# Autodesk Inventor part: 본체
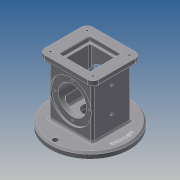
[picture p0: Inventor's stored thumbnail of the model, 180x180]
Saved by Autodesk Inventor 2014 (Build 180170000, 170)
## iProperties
Created: 2019-08
Part Number: 본체
Material: Generic
Document SubType Name: Modeling
Designer: kb542-17
Density: 1 g/cm^3
Appearance: Default
Mass: 384.755 g
Surface Area: 783.577 cm^2
Volume: 384.755 cm^3
Author: kb542-17
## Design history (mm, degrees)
sketch "스케치1"
  geometry: L1 (-37, 33)-(37, 33); L2 (37, 33)-(37, -33); L3 (37, -33)-(-37, -33); L4 (-37, -33)-(-37, 33); L5 (-37, 33)-(37, -33); L6 (37, 33)-(-37, -33); 1 further point
  constraints: 12 end point, 2 midpoint, 2 parallel, 1 horizontal, 1 perpendicular
  dimensions: "d0" = 66 distance of L1.end L2.end; "d1" = 74 distance of L1.start L1.end
extrude "돌출1" new body sketch "스케치1" stored distance "d2" = 88; taper "d3" = 0 deg
sketch "스케치2"
  geometry: L1 (-46, 41)-(46, 41); L2 (46, 41)-(46, -41); L3 (46, -41)-(-46, -41); L4 (-46, -41)-(-46, 41); L5 (-46, 41)-(46, -41); L6 (46, 41)-(-46, -41); 1 further point
  constraints: 12 end point, 2 midpoint, 2 parallel, 1 horizontal, 1 perpendicular
  dimensions: "d4" = 82 distance of L1.end L2.end; "d5" = 92 distance of L1.start L1.end
extrude "돌출2" join sketch "스케치2" distance "d6" = 10; taper "d7" = 0 deg
sketch "스케치3"
  geometry: C1 r 67.5 at (0, 0); 1 further point
  constraints: 1 centre point, 1 coincident
  dimensions: "d8" = 135 diameter of C1
extrude "돌출3" join sketch "스케치3" distance "d9" = 10; taper "d10" = 0 deg
sketch "스케치4"
  geometry: L1 (-33, 44)-(-33, -44) reference; L2 (33, -44)-(33, 44) reference; L3 (-33, 0)-(33, 0); L4 (-33, 35)-(-30, 35); L5 (-30, 35)-(-30, 24); L6 (-30, 24)-(30, 24); L7 (30, 24)-(30, 35); L8 (30, 35)-(33, 35); 2 further points
  constraints: 12 end point, 3 midpoint, 3 parallel, 2 point on line, 1 coincident, 1 collinear, 1 perpendicular
  dimensions: "d11" = 3 distance between parallel lines of L1 L5; "d12" = 3 distance between parallel lines of L2 L7; "d13" = 70 diameter of L4 L3; "d14" = 48 diameter of L6 L3; "d15" = 70 diameter of L8 L3
revolve "회전1" sketch "스케치4" stored, may be unused: angle "d16" = 90 deg
sketch "스케치5"
  geometry: C1 r 67.5 at (0, 0) reference; C2 r 25 at (0, 0)
  constraints: 1 centre point, 1 coincident
  dimensions: "d17" = 50 diameter of C2
extrude "돌출4" cut sketch "스케치5" distance "d18" = 18; taper "d19" = 0 deg
sketch "스케치6"
  geometry: L1 (-26, 26)-(26, 26); L2 (26, 26)-(26, -26); L3 (26, -26)-(-26, -26); L4 (-26, -26)-(-26, 26); L5 (-26, 26)-(26, -26); L6 (26, 26)-(-26, -26); 1 further point
  constraints: 12 end point, 2 midpoint, 2 parallel, 1 horizontal, 1 perpendicular
  dimensions: "d20" = 52 distance of L1.end L2.end; "d21" = 52 distance of L1.start L1.end
extrude "돌출5" cut sketch "스케치6" distance "d22" = 8; taper "d23" = 0 deg
sketch "스케치7"
  geometry: L1 (-22, 22)-(22, 22); L2 (22, 22)-(22, -22); L3 (22, -22)-(-22, -22); L4 (-22, -22)-(-22, 22); L5 (-22, 22)-(22, -22); L6 (22, 22)-(-22, -22); 1 further point
  constraints: 12 end point, 2 midpoint, 2 parallel, 1 horizontal, 1 perpendicular
  dimensions: "d24" = 44 distance of L1.start L1.end; "d25" = 44 distance of L1.end L2.end
extrude "돌출6" cut sketch "스케치7" distance "d26" = 74; taper "d27" = 0 deg
sketch "스케치8"
  geometry: C1 r 25 at (0, 0) reference; C2 r 12.5 at (0, 0)
  constraints: 1 centre point, 1 coincident
  dimensions: "d28" = 25 diameter of C2
extrude "돌출7" cut sketch "스케치8" stored distance "d29" = 74; taper "d30" = 0 deg
sketch "스케치9"
  geometry: C1 r 24 at (0, 0) reference; 1 further point
  constraints: 1 vertical alignment
  dimensions: "d31" = 29 distance of C1.centre point (0, 29)
hole "구멍1" sketch "스케치9" at (0, 29) diameter "d32" = 3.242; stored, may be unused: countersink angle "d36" = 90 deg, drill point angle "d38" = 118 deg; dims "d33" = 4, "d34" = 4, "d35" = 2, "d37" = 6
sketch "스케치10"
  geometry: C1 r 35 at (0, 0) reference; 1 further point
  constraints: 1 vertical alignment
  dimensions: "d42" = 29 distance of C1.centre point (0, -29)
hole "구멍2" sketch "스케치10" at (0, -29) diameter "d43" = 3.242; stored, may be unused: countersink angle "d47" = 90 deg, drill point angle "d49" = 118 deg; dims "d44" = 4, "d45" = 4, "d46" = 2, "d48" = 6
fillet "모깎기1" dims "d53" = 10
sketch "스케치11"
  geometry: A1 r 10 centre (-36, 31) between (-36, 41) and (-46, 31) reference; A2 r 10 centre (-36, -31) between (-46, -31) and (-36, -41) reference; A3 r 10 centre (36, -31) between (36, -41) and (46, -31) reference; A4 r 10 centre (36, 31) between (46, 31) and (36, 41) reference; 5 further points
  constraints: 4 coincident
chamfer "모따기1" distance "d61" = 3; stored, may be unused: second distance "d62" = 2, angle "d63" = 45 deg
sketch "스케치13"
  geometry: C1 r 64.5 at (0, 0) reference; 1 further point
  constraints: 1 vertical alignment
  dimensions: "d64" = 59 distance of point (0, 59) C1.centre
hole "구멍4" sketch "스케치13" at (0, 59) diameter "d65" = 9; stored, may be unused: countersink angle "d69" = 90 deg, drill point angle "d71" = 118 deg; dims "d66" = 4, "d67" = 4, "d68" = 2, "d70" = 6
sketch "스케치14"
  geometry: L1 (98, -34.5)-(98, 100.5) reference; 3 further points
  constraints: 2 horizontal alignment
  dimensions: "d75" = 37 distance from line of L1 point (61, 33); "d76" = 43 distance of point (61, 33) point (18, 33)
hole "구멍5" sketch "스케치14" diameter "d77" = 4.917; stored, may be unused: countersink angle "d81" = 90 deg, drill point angle "d83" = 118 deg; dims "d78" = 6, "d79" = 4, "d80" = 2, "d82" = 43 (= d76)
hole "구멍6" sketch "스케치14" diameter "d84" = 4.917; stored, may be unused: countersink angle "d88" = 90 deg, drill point angle "d90" = 118 deg; dims "d85" = 6, "d86" = 4, "d87" = 2, "d89" = 43 (= d76)
sketch "스케치15"
  geometry: C1 r 64.5 at (0, 0) reference; C2 r 59 at (0, 0)
  constraints: 1 centre point, 1 coincident, 1 other
  dimensions: "d91" = 118 diameter of C2
feature "엠보싱1" sketch "스케치15" dims "d92" = 0.5, "d93" = 0
fillet "모깎기2" dims "d94" = 3
fillet "모깎기3" dims "d95" = 3
fillet "모깎기4" dims "d96" = 3
chamfer "모따기2" distance "d97" = 1; stored, may be unused: second distance "d98" = 2, angle "d99" = 45 deg
fillet "모깎기5" dims "d100" = 3
fillet "모깎기6" dims "d101" = 3
fillet "모깎기7" dims "d102" = 3
fillet "모깎기8" dims "d103" = 3
hole "구멍7" sketch "스케치11" diameter "d104" = 3.242; stored, may be unused: countersink angle "d108" = 90 deg, drill point angle "d110" = 118 deg; dims "d105" = 4, "d106" = 4, "d107" = 2, "d109" = 6
node "솔리드1"
pattern_circular "원형 패턴1" dims angle "d40" = 360 deg
pattern_circular "원형 패턴2" dims angle "d51" = 360 deg
pattern_circular "원형 패턴3" dims angle "d73" = 180 deg
